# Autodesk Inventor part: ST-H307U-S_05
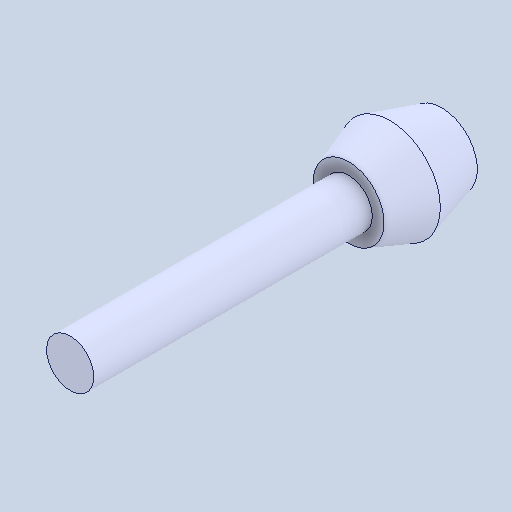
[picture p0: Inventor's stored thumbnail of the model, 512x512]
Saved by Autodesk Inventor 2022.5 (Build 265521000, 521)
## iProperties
Created: 2024-07
Part Number: ST-H307U-S_05
Material: 一般
Document SubType Name: Modeling
Designer: ImaoCorp
Density: 1 g/cm^3
Appearance: 既定
Author: ImaoCorp
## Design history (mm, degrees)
feature "ST-H307U-S_05"
node "ソリッド1"
